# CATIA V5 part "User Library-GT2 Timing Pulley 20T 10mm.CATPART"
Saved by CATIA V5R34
Part number: 44EEF92A-FFC0-4734-A5A9-2981DF16A77E
Revision: ANY
Definition: UNKNOWN
Nomenclature: 44EEF92A-FFC0-4734-A5A9-2981DF16A77E
Source: Unknown
Bounding box of the stored display mesh (mm): x -8 to 8, y -8 to 8, z -13 to 7
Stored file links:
  C:\Users\Apolinar\Desktop\cnc\User Library-GT2 Timing Pulley 20T 10mm.CATPART
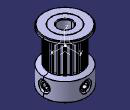
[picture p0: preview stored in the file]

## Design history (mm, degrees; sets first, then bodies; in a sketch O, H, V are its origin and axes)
AxisSystem1: origin (0, 0, 0), X (1, 0, 0), Y (0, 1, 0), Z (0, 0, 1)
Body1 "M4x0.7X5mm - flat-tip Set screw.step-1-solid1" (main body)
  Solid1: solid without history
Body2 "M4x0.7X5mm - flat-tip Set screw.step-2-solid1"
  Solid2: solid without history
Body3 "GT2 Timing Pulley 20T 10mm - Hole_5mm.step-1-solid1"
  Solid3: solid without history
